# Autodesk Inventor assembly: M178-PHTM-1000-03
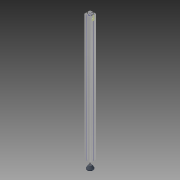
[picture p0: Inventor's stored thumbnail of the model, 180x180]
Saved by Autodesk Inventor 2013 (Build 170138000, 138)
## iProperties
Created: 2004-11
Part Number: M178-PHTM-1000-03
Document SubType Name: Assembly
Designer: Autodesk, Inc.
Manufacturer: Standard
Standards Organization: Custom
Description: PHANTOM, TABLE, LEGS
Mass: 1519.64 g
Surface Area: 3943.48 cm^2
Volume: 557.121 cm^3
Density: 2.72767 g/cm^3
CAGE: 1LJX3
Dept. ID: Product Design
Description #2: ---
Finish #1: ---
Finish #2: ---
Material ID: ---
Project Number: ---
Author: Autodesk, Inc.
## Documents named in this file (8)
- Z:\_DATEN\Test Station\Components\M178-1000_Leg_Phantom.iam
- Z:\_DATEN\Test Station\Components\21-009.ipt
- Z:\_DATEN\Test Station\Components\M178-1004.ipt
- Z:\_DATEN\Test Station\Components\20-004.iam
- Z:\_DATEN\Test Station\Components\24-706-8.ipt
- C:\Users\kelleyb.ADS\Desktop\Samples MIGRATED 2009 224 RTM_1\Standard Parts\Test Station Content\Misc Hardware\21-0xx Knuckle Foot.ipt
- C:\Users\kelleyb.ADS\Desktop\Samples MIGRATED 2009 224 RTM_1\Standard Parts\Test Station Content\Fastners\24-7X6 Hexagon Nuts.ipt
- C:\Users\kelleyb.ADS\Desktop\Samples MIGRATED 2009 224 RTM_1\Standard Parts\Test Station Content\Extrusions\40 Series Profiles.ipt
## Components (4 placed, 4 different names)
1. 21-009:1
2. 24-706-8:1
3. M178-1004:1
4. 20-004:1 [sub-assembly]
